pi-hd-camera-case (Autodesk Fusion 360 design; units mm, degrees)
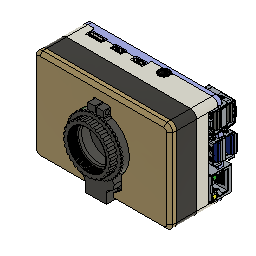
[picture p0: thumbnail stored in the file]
parameter "thickness" = 1.5
parameter "gap" = 0.2
parameter "boxWidth" = 86
parameter "boxHeight" = 57
parameter "boxDepth" = 50
base_feature "Base Feature1"
base_feature "Base Feature1"
base_feature "Base Feature1"
base_feature "Base Feature1"
base_feature "Base Feature1"
base_feature "Base Feature1"
base_feature "Base Feature1"
base_feature "Base Feature1"
base_feature "Base Feature1"
base_feature "Base Feature1"
base_feature "Base Feature1"
place_component Linear Dimension-11 20
base_feature "Base Feature1"
base_feature "Base Feature1"
base_feature "Base Feature1"
base_feature "Base Feature1"
base_feature "Base Feature1"
base_feature "Base Feature1"
base_feature "Base Feature1"
as_built_joint "As-built1"
base_feature "Base Feature1"
sketch "base" plane through (0, 0, 0) normal (0, 1, 0) x axis (1, 0, 0)
  line L1 (43, -28.5) -> (-43, -28.5)
  line L2 (43, 28.5) -> (43, -28.5)
  line L3 (-43, 28.5) -> (43, 28.5)
  line L4 (-43, -28.5) -> (-43, 28.5)
  line L5 (0, 0) -> (0, -28.5)
  line L6 (43, 0) -> (0, 0)
  line L7 (15, -15) -> (-15, -15)
  line L8 (-15, 15) -> (-15, -15)
  line L9 (15, 15) -> (15, -15)
  line L10 (-15, 15) -> (15, 15)
  line L11 (0, 0) -> (0, 15)
  line L12 (0, 0) -> (-15, 0)
  line L13 (-44.5, 30) -> (44.5, 30)
  line L14 (-44.5, -30) -> (-44.5, 30)
  line L15 (44.5, -30) -> (-44.5, -30)
  line L16 (44.5, 30) -> (44.5, -30)
  circle C1 centre (-39, -24.5) radius 1.5
  circle C2 centre (-15, -15) radius 1.5
  circle C3 centre (15, -15) radius 1.5
  circle C4 centre (-15, 15) radius 1.5
  circle C5 centre (15, 15) radius 1.5
  point P6 (0, -28.5)
  point P1 (0, 0)
  point P7 (0, 0)
  point P8 (43, 0)
  point P10 (-15, -15)
  point P11 (-15, -15)
  point P12 (15, -15)
  point P13 (15, -15)
  point P14 (-15, -15)
  point P15 (-15, 15)
  point P16 (-15, 15)
  point P17 (15, -15)
  point P19 (-15, 15)
  point P18 (15, 15)
  point P20 (15, 15)
  point P21 (0, 15)
  point P22 (0, 0)
  point P23 (-15, 0)
  point P24 (0, 0)
  point P2 (-43, -28.5)
  point P3 (43, -28.5)
  point P5 (-43, 28.5)
  point P9 (-39, -24.5)
  horizontal L1
  vertical L2
  horizontal L3
  vertical L4
  midpoint L1 P6
  coincident P1 P7
  midpoint L2 P8
  vertical L5
  horizontal L6
  coincident P10 P11
  horizontal L7
  coincident P12 P13
  coincident P10 P14
  perpendicular L7 L8
  coincident P15 P16
  coincident P13 P17
  perpendicular L7 L9
  coincident P16 P19
  perpendicular L9 L10
  coincident P18 P20
  midpoint L10 P21
  coincident P1 P22
  vertical L11
  midpoint L8 P23
  coincident P1 P24
  horizontal L12
  dimension "d6" distance P2 P3 = 86 (= "boxWidth")
  dimension "d7" distance P2 P5 = 57 (= "boxHeight")
  dimension "d8" diameter C1 = 3
  dimension "d9" distance L1 P9 = 4
  dimension "d10" distance L4 P9 = 4
  dimension "d11" diameter C2 = 3
  dimension "d12" diameter C3 = 3
  dimension "d13" distance P11 P12 = 30
  dimension "d14" distance P14 P15 = 30
  dimension "d15" diameter C4 = 3
  dimension "d16" diameter C5 = 3
  dimension "d97" = 1.5 (= "thickness")
  dimension "d33" OffsetX = 0
  dimension "d34" OffsetY = 0
  dimension "d35" OffsetZ = 0
  dimension "d36" AngleZ = 0
  dimension "d79" OffsetX = 0
  dimension "d80" OffsetY = 0
  dimension "d81" OffsetZ = 0
  dimension "d82" AngleZ = 0
joint "Assemble1" OffsetX 0 OffsetY 0 OffsetZ 0 AngleZ 0 alignAngle 0 alignOffsetX 0 alignOffsetY 0 alignOffsetZ 0
joint "Assemble2" OffsetX 0 OffsetY 0 OffsetZ 0 AngleZ 0 alignAngle 0 alignOffsetX 0 alignOffsetY 0 alignOffsetZ -17 OffsetX 0 OffsetY 0 OffsetZ 0 AngleZ 0 OffsetX 0 OffsetY 0 OffsetZ 0 AngleZ 0
sketch "Sketch1" plane through (0, 0, 0) normal (0, 1, 0) x axis (1, 0, 0)
  line L1 (19, -24.5) -> (-39, -24.5)
  line L2 (-39, 24.5) -> (19, 24.5)
  line L3 (-39, -24.5) -> (-39, 24.5)
  line L4 (15, -15) -> (-15, -15)
  line L5 (15, 14.9769) -> (15, -15)
  line L6 (-15, 14.9769) -> (15, 14.9769)
  line L7 (-15, -15) -> (-15, 14.9769)
  line L8 (-39, -9) -> (-15, -9)
  line L9 (-9, -24.5) -> (-9, -15)
  line L10 (-9, 24.5) -> (-9, 14.9769)
  line L11 (39, -24.5) -> (19, -24.5)
  line L12 (39, 24.5) -> (39, -24.5)
  line L13 (19, 24.5) -> (39, 24.5)
  line L14 (39, -9) -> (15, -9)
  line L15 (9, -15) -> (9, -24.5)
  line L16 (-15, 8.9769) -> (-39, 8.9769)
  line L17 (39, 8.9769) -> (15, 8.9769)
  line L18 (9, 24.5) -> (9, 14.9769)
  circle C1 centre (-39, -24.5) radius 1.35
  circle C2 centre (19, -24.5) radius 1.35
  circle C3 centre (15, -15) radius 1.25
  circle C4 centre (-15, -15) radius 1.25
  circle C5 centre (-15, 14.9769) radius 1.25
  circle C6 centre (15, 14.9769) radius 1.25
  circle C7 centre (19, 24.5) radius 1.35
  circle C8 centre (-39, 24.5) radius 1.35
  circle C9 centre (-39, -24.5) radius 1.75
  circle C10 centre (-39, -24.5) radius 3.25
  circle C11 centre (-39, 24.5) radius 1.75
  circle C12 centre (-39, 24.5) radius 3.25
  circle C13 centre (-15, 14.9769) radius 1.5
  circle C14 centre (-15, 14.9769) radius 3
  circle C15 centre (-15, -15) radius 1.5
  circle C16 centre (-15, -15) radius 3
  circle C17 centre (19, -24.5) radius 1.75
  circle C18 centre (19, -24.5) radius 3.25
  circle C19 centre (15, -15) radius 1.5
  circle C20 centre (15, -15) radius 3
  circle C21 centre (15, 14.9769) radius 1.5
  circle C22 centre (15, 14.9769) radius 3
  circle C23 centre (19, 24.5) radius 1.75
  circle C24 centre (19, 24.5) radius 3.25
  circle C25 centre (39, 24.5) radius 1.75
  circle C26 centre (39, 24.5) radius 3.25
  circle C27 centre (39, -24.5) radius 1.75
  circle C28 centre (39, -24.5) radius 3.25
  circle C29 centre (-29, 24.5) radius 1.75
  circle C30 centre (-29, 24.5) radius 3.25
  circle C31 centre (-29, -24.5) radius 1.75
  circle C32 centre (-29, -24.5) radius 3.25
  point P2 (-39, -24.5)
  point P10 (-39, -24.5)
  point P3 (19, -24.5)
  point P11 (19, -24.5)
  point P8 (19, 24.5)
  point P12 (19, 24.5)
  point P9 (-39, 24.5)
  point P13 (-39, 24.5)
  point P5 (-15, -15)
  point P14 (-15, -15)
  point P4 (15, -15)
  point P15 (15, -15)
  point P7 (15, 14.9769)
  point P16 (15, 14.9769)
  point P6 (-15, 14.9769)
  point P17 (-15, 14.9769)
  point P18 (-15, -15)
  point P20 (-39, -9)
  point P22 (-9, -24.5)
  point P24 (-9, 24.5)
  point P25 (-39, -24.5)
  point P27 (-39, 24.5)
  point P31 (-15, -15)
  point P33 (19, -24.5)
  point P37 (15, 14.9769)
  point P39 (19, 24.5)
  point P41 (19, -24.5)
  point P44 (19, 24.5)
  point P46 (39, -9)
  point P47 (9, -24.5)
  point P48 (9, -15)
  point P49 (-39, 8.9769)
  point P50 (-15, 8.9769)
  point P51 (15, 8.9769)
  point P52 (39, 8.9769)
  point P53 (9, 14.9769)
  point P54 (9, 24.5)
  point P43 (39, 24.5)
  point P55 (39, 24.5)
  point P42 (39, -24.5)
  point P57 (39, -24.5)
  point P61 (-29, -24.5)
  point P59 (-29, 24.5)
  point P35 (15, -15)
  point P29 (-15, 14.9769)
  point P62 (-29, -24.5)
  point P63 (-39, -24.5)
  point P60 (-29, 24.5)
  coincident P2 P10
  coincident P3 P11
  coincident P8 P12
  coincident P9 P13
  coincident P5 P14
  coincident P4 P15
  coincident P7 P16
  coincident P6 P17
  coincident P5 P18
  coincident L3 P20
  perpendicular L3 L8
  coincident L1 P22
  perpendicular L1 L9
  coincident L2 P24
  perpendicular L6 L10
  coincident P10 P25
  coincident P13 P27
  concentric C5 C13
  coincident P18 P31
  coincident P11 P33
  concentric C3 C19
  coincident P16 P37
  coincident P12 P39
  coincident P33 P41
  parallel L1 L11
  perpendicular L1 L12
  coincident P39 P44
  perpendicular L12 L13
  coincident L12 P46
  perpendicular L12 L14
  coincident L1 P47
  coincident L4 P48
  perpendicular L4 L15
  coincident L3 P49
  coincident L7 P50
  perpendicular L7 L16
  coincident L5 P51
  coincident L12 P52
  perpendicular L12 L17
  coincident L6 P53
  coincident L2 P54
  perpendicular L2 L18
  coincident P43 P55
  coincident P42 P57
  coincident L1 P61
  coincident L2 P59
  dimension "d42" diameter C9 = 3.5
  dimension "d43" = 1.5 (= "thickness")
  dimension "d44" diameter C11 = 3.5
  dimension "d45" = 1.5 (= "thickness")
  dimension "d46" diameter C13 = 3
  dimension "d47" distance C13 = 1.5 (= "thickness")
  dimension "d48" diameter C15 = 3
  dimension "d49" distance C15 = 1.5 (= "thickness")
  dimension "d50" diameter C17 = 3.5
  dimension "d51" = 1.5 (= "thickness")
  dimension "d52" diameter C19 = 3
  dimension "d53" distance C19 = 1.5 (= "thickness")
  dimension "d54" diameter C21 = 3
  dimension "d55" distance C21 = 1.5 (= "thickness")
  dimension "d56" diameter C23 = 3.5
  dimension "d57" = 1.5 (= "thickness")
  dimension "d63" distance P41 P42 = 20
  dimension "d89" distance P35 L14 = 6
  dimension "d90" distance P16 L17 = 6
  dimension "d91" distance P14 L8 = 6
  dimension "d92" distance P29 L16 = 6
  dimension "d93" distance L10 P29 = 6
  dimension "d94" distance P16 L18 = 6
  dimension "d95" distance P35 L15 = 6
  dimension "d96" distance P14 L9 = 6
  dimension "d150" diameter C25 = 3.5
  dimension "d151" = 1.5 (= "thickness")
  dimension "d153" diameter C27 = 3.5
  dimension "d154" = 1.5 (= "thickness")
  dimension "d156" diameter C29 = 3.5
  dimension "d158" = 1.5 (= "thickness")
  dimension "d159" diameter C31 = 3.5
  dimension "d160" = 1.5 (= "thickness")
  dimension "d162" distance P62 P63 = 10
  dimension "d266" distance P13 P60 = 10
extrude "Extrude3" new body blind -2 from offset -3
thicken "Thicken2" Thickness 1
extrude "Extrude4" add sketch "Sketch1" profile of L1 L2 L3 C9 C10 C11 C12 C17 C18 C23 C24 L11 L13 to an object
extrude "Extrude6" sketch "Sketch1" profile of L1 L2 L4 L5 L6 L7 C13 C14 C15 C16 C19 C20 C21 C22 L11 L12 L13 C25 C26 C27 C28 C29 C30 C31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 to an object
extrude "Extrude5" cut sketch "Sketch1" profile of L1 L2 L3 L4 L5 L6 L7 C9 C11 C13 C15 C17 C19 C21 C23 L11 L12 L13 C25 C27 C29 C31 to an object
fillet "Fillet1" radius 1
sketch "Sketch1" plane through (0, 0, 0) normal (0, 1, 0) x axis (1, 0, 0)
  line L1 (-15, -12.1132) -> (-12.5, -13.5566)
  line L2 (-17.5, -13.5566) -> (-15, -12.1132)
  line L3 (-17.5, -16.4434) -> (-17.5, -13.5566)
  line L4 (-15, -17.8868) -> (-17.5, -16.4434)
  line L5 (-12.5, -16.4434) -> (-15, -17.8868)
  line L6 (-12.5, -13.5566) -> (-12.5, -16.4434)
  line L7 (0, -10) -> (0, 0)
  line L8 (17.5, -16.4434) -> (17.5, -13.5566)
  line L9 (15, -17.8868) -> (17.5, -16.4434)
  line L10 (12.5, -16.4434) -> (15, -17.8868)
  line L11 (12.5, -13.5566) -> (12.5, -16.4434)
  line L12 (15, -12.1132) -> (12.5, -13.5566)
  line L13 (17.5, -13.5566) -> (15, -12.1132)
  line L14 (10, 0) -> (0, 0)
  line L15 (17.5, 16.4434) -> (17.5, 13.5566)
  line L16 (15, 17.8868) -> (17.5, 16.4434)
  line L17 (12.5, 16.4434) -> (15, 17.8868)
  line L18 (12.5, 13.5566) -> (12.5, 16.4434)
  line L19 (15, 12.1132) -> (12.5, 13.5566)
  line L20 (17.5, 13.5566) -> (15, 12.1132)
  line L21 (-17.5, 16.4434) -> (-17.5, 13.5566)
  line L22 (-15, 17.8868) -> (-17.5, 16.4434)
  line L23 (-12.5, 16.4434) -> (-15, 17.8868)
  line L24 (-12.5, 13.5566) -> (-12.5, 16.4434)
  line L25 (-17.5, 13.5566) -> (-15, 12.1132)
  line L26 (-15, 12.1132) -> (-12.5, 13.5566)
  circle C1 centre (-15, -15) radius 1.5
  circle C2 centre (15, -15) radius 1.5
  circle C3 centre (15, 14.9769) radius 1.5
  circle C4 centre (-15, 14.9769) radius 1.5
  point P2 (-15, -15)
  point P12 (-15, -15)
  point P1 (0, 0)
  point P13 (0, 0)
  point P6 (-12.5, -13.5566)
  point P19 (12.5, -13.5566)
  point P7 (-15, -12.1132)
  point P20 (15, -12.1132)
  point P8 (-17.5, -13.5566)
  point P15 (17.5, -13.5566)
  point P9 (-17.5, -16.4434)
  point P16 (17.5, -16.4434)
  point P10 (-15, -17.8868)
  point P17 (15, -17.8868)
  point P11 (-12.5, -16.4434)
  point P18 (12.5, -16.4434)
  point P21 (0, 0)
  point P33 (-12.5, 13.5566)
  point P34 (-15, 12.1132)
  point P29 (-17.5, 13.5566)
  point P30 (-17.5, 16.4434)
  point P31 (-15, 17.8868)
  point P32 (-12.5, 16.4434)
  point P23 (17.5, 13.5566)
  point P24 (17.5, 16.4434)
  point P25 (15, 17.8868)
  point P26 (12.5, 16.4434)
  point P27 (12.5, 13.5566)
  point P28 (15, 12.1132)
  coincident P2 P12
  vertical L6
  coincident P1 P13
  vertical L7
  symmetric P6 L7 P19
  symmetric P7 L7 P20
  symmetric P8 L7 P15
  symmetric P9 L7 P16
  symmetric P10 L7 P17
  symmetric P11 L7 P18
  coincident P1 P21
  perpendicular L7 L14
  symmetric P6 L14 P33
  symmetric P7 L14 P34
  symmetric P8 L14 P29
  symmetric P9 L14 P30
  symmetric P10 L14 P31
  symmetric P11 L14 P32
  symmetric P15 L14 P23
  symmetric P16 L14 P24
  symmetric P17 L14 P25
  symmetric P18 L14 P26
  symmetric P19 L14 P27
  symmetric P20 L14 P28
  dimension "d85" distance P12 L6 = 2.5
extrude "Extrude1" sketch "Sketch1" profile of C1 C2 C3 C4 L1 L2 L3 L4 L5 L6 L8 L9 L10 L11 L12 L13 L15 L16 L17 L18 L19 L20 L21 L22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 blind -12
base_feature "Base Feature1"
rectangular_pattern "" uSpaceDistance 7 vSpaceDistance 0
joint "Assemble3" alignAngle 0 alignOffsetX 0 alignOffsetY 0 alignOffsetZ 0
joint "Assemble4" alignAngle 0 alignOffsetX 0 alignOffsetY 0 alignOffsetZ 0
joint "Assemble5" alignAngle 0 alignOffsetX 0 alignOffsetY 0 alignOffsetZ 0
joint "Assemble6" alignAngle 0 alignOffsetX 0 alignOffsetY 0 alignOffsetZ 0
joint "Assemble7" OffsetX 0 OffsetY 0 OffsetZ 0 AngleZ 0 alignAngle 0 alignOffsetX 0 alignOffsetY 0 alignOffsetZ 0
joint "Assemble8" OffsetX 0 OffsetY 0 OffsetZ 0 AngleZ 0 alignAngle 0 alignOffsetX 0 alignOffsetY 0 alignOffsetZ 0
joint "Assemble9" OffsetX 0 OffsetY 0 OffsetZ 0 AngleZ 0 alignAngle 0 alignOffsetX 0 alignOffsetY 0 alignOffsetZ 0
joint "Assemble10" OffsetX 0 OffsetY 0 OffsetZ 0 AngleZ 0 alignAngle 0 alignOffsetX 0 alignOffsetY 0 alignOffsetZ 0
base_feature "Base Feature1"
rectangular_pattern "ꨁ225" uSpaceDistance 9 vSpaceDistance 0
joint "Assemble11" OffsetX 0 OffsetY 0 OffsetZ 0 AngleZ 0 alignAngle 0 alignOffsetX 0 alignOffsetY 0 alignOffsetZ 0
joint "Assemble12" OffsetX 0 OffsetY 0 OffsetZ 0 AngleZ 0 alignAngle 0 alignOffsetX 0 alignOffsetY 0 alignOffsetZ 0
joint "Assemble13" OffsetX 0 OffsetY 0 OffsetZ 0 AngleZ 0 alignAngle 0 alignOffsetX 0 alignOffsetY 0 alignOffsetZ 0
joint "Assemble14" OffsetX 0 OffsetY 0 OffsetZ 0 AngleZ 0 alignAngle 0 alignOffsetX 0 alignOffsetY 0 alignOffsetZ 0
base_feature "Base Feature1"
rectangular_pattern "甁" uSpaceDistance 7 vSpaceDistance 0
joint "Assemble15" alignAngle 0 alignOffsetX 0 alignOffsetY 0 alignOffsetZ 0
joint "Assemble16" alignAngle 0 alignOffsetX 0 alignOffsetY 0 alignOffsetZ 0
joint "Assemble17" alignAngle 0 alignOffsetX 0 alignOffsetY 0 alignOffsetZ 0
joint "Assemble18" alignAngle 0 alignOffsetX 0 alignOffsetY 0 alignOffsetZ 0
extrude "Extrude1" new body sketch "base" profile of L1 L2 L3 L4 L16 L14 L15 L13 blind -14 from offset 7
fillet "Fillet2" radius 2.5 4
sketch "usb ports" plane through (44.5, 0, 0) normal (1, 0, 0) x axis (0, 1, 0)
  line L1 (7, -26) -> (7, 26)
  line L2 (1, 26) -> (7, 26)
  line L3 (1, -26) -> (1, 26)
  line L4 (7, -26) -> (1, -26)
  point P7 (7, -26)
  point P5 (1, -26)
  point P6 (1, -26)
  point P3 (7, -26)
  point P2 (7, 26)
  point P8 (7, 26)
  point P4 (1, 26)
  perpendicular L1 L2
  perpendicular L2 L3
  coincident L1 P7
  perpendicular L1 L4
  coincident P5 P6
  coincident P3 L4
  coincident P2 P8
  dimension "d122" distance P2 P4 = 6
extrude "Extrude4" cut sketch "usb ports" against normal blind 3
sketch "top ports" plane through (0, 0, 30) normal (0, 0, 1) x axis (-1, 0, 0)
  line L1 (7, -1) -> (-1, -1)
  line L2 (7, -7) -> (7, -1)
  line L3 (-1, -7) -> (7, -7)
  line L4 (-1, -1) -> (-1, -7)
  line L5 (20, -1) -> (13, -1)
  line L6 (20, -7) -> (20, -1)
  line L7 (13, -7) -> (20, -7)
  line L8 (13, -1) -> (13, -7)
  line L9 (36, -1) -> (26, -1)
  line L10 (36, -7) -> (36, -1)
  line L11 (26, -7) -> (36, -7)
  line L12 (26, -1) -> (26, -7)
  circle C1 centre (-11.5, -4.59) radius 2.1
  circle C2 centre (-11.5, -4.59) radius 3.5
  concentric C1 C2
  horizontal L1
  vertical L2
  horizontal L3
  vertical L4
  horizontal L5
  vertical L6
  horizontal L7
  vertical L8
  horizontal L9
  vertical L10
  horizontal L11
  vertical L12
  dimension "d123" diameter C2 = 7
extrude "Extrude5" cut sketch "top ports" no distance stored
fillet "Fillet3" radius 1
extrude "Extrude6" cut of existing geometry blind -3
sketch "sdcard" plane through (-44.5, 0, 0) normal (-1, 0, 0) x axis (0, -1, 0)
  line L1 (2, 7.3) -> (-1, 7.3)
  line L2 (2, -7.7) -> (2, 7.3)
  line L3 (-1, -7.7) -> (2, -7.7)
  line L4 (-1, 7.3) -> (-1, -7.7)
  line L5 (0, -0.2) -> (-1, -0.2)
  line L6 (0, 0) -> (0, -0.2)
  line L7 (5, 4.3) -> (2, 4.3)
  line L8 (5, -4.7) -> (5, 4.3)
  line L9 (2, -4.7) -> (5, -4.7)
  line L10 (2, -0.2) -> (5, -0.2)
  line L11 (-4, 4.3) -> (-1, 4.3)
  line L12 (-4, -4.7) -> (-4, 4.3)
  line L13 (-1, -4.7) -> (-4, -4.7)
  line L14 (-1, -0.2) -> (-4, -0.2)
  point P6 (-1, -0.2)
  point P1 (0, 0)
  point P8 (0, 0)
  point P9 (2, 4.3)
  point P12 (2, -4.7)
  point P13 (5, -0.2)
  point P14 (2, -0.2)
  point P15 (-1, 4.3)
  point P18 (-1, -4.7)
  point P19 (-4, -0.2)
  point P3 (2, 7.3)
  point P4 (2, -7.7)
  point P2 (-1, 7.3)
  point P7 (0, -0.2)
  point P10 (5, 4.3)
  point P11 (5, -4.7)
  point P16 (-4, 4.3)
  point P17 (-4, -4.7)
  horizontal L1
  vertical L2
  horizontal L3
  vertical L4
  midpoint L4 P6
  perpendicular L4 L5
  coincident P1 P8
  perpendicular L5 L6
  coincident L2 P9
  perpendicular L2 L7
  perpendicular L7 L8
  coincident L2 P12
  perpendicular L2 L9
  midpoint L8 P13
  midpoint L2 P14
  horizontal L10
  coincident L4 P15
  perpendicular L4 L11
  perpendicular L11 L12
  coincident L4 P18
  perpendicular L4 L13
  midpoint L12 P19
  horizontal L14
  dimension "d129" distance P3 P4 = 15
  dimension "d130" distance P2 P3 = 3
  dimension "d133" distance P6 P7 = 1
  dimension "d176" distance P10 P11 = 9
  dimension "d177" distance P9 P10 = 3
  dimension "d179" distance P16 P17 = 9
  dimension "d180" distance P15 P16 = 3
  dimension "d417" distance P7 P8 = 0.2
extrude "Extrude7" cut sketch "sdcard" profile of L1 L2 L3 L4 L7 L8 L9 L11 L12 L13 no distance stored
fillet "Fillet5" radius 1.5 1.6
fillet "Fillet6" radius 1
sketch "tabs" plane through (0, -7, 0) normal (0, -1, 0) x axis (1, 0, 0)
  line L1 (44.5, 30) -> (-44.5, 30)
  line L2 (44.5, -30) -> (44.5, 30)
  line L3 (-44.5, -30) -> (44.5, -30)
  line L4 (-44.5, 30) -> (-44.5, -30)
  line L5 (0, 0) -> (0, 30)
  line L6 (44.5, 0) -> (0, 0)
  line L7 (-32.25, 21.25) -> (-32.25, 30)
  line L8 (-25.75, 21.25) -> (-32.25, 21.25)
  line L9 (-25.75, 30) -> (-25.75, 21.25)
  line L10 (-29, 24.5) -> (-29, 21.25)
  line L11 (-32.25, -21.25) -> (-32.25, -30)
  line L12 (-25.75, -21.25) -> (-32.25, -21.25)
  line L13 (-25.75, -30) -> (-25.75, -21.25)
  line L14 (-29, -21.25) -> (-29, -24.5)
  line L15 (35.75, -21.25) -> (44.5, -21.25)
  line L16 (35.75, -27.75) -> (35.75, -21.25)
  line L17 (44.5, -27.75) -> (35.75, -27.75)
  line L18 (39, -24.5) -> (35.75, -24.5)
  line L19 (35.75, 21.25) -> (35.75, 30)
  line L20 (44.5, 21.25) -> (35.75, 21.25)
  line L21 (39, 24.5) -> (35.75, 24.5)
  line L22 (43, -26) -> (43, 26)
  line L23 (40.5, 28.5) -> (-40.5, 28.5)
  circle C1 centre (-29, 24.5) radius 1.75
  circle C2 centre (-29, -24.5) radius 1.75
  circle C3 centre (39, 24.5) radius 1.75
  circle C4 centre (39, -24.5) radius 1.75
  arc A1 centre (40.5, 26) radius 2.5 clockwise from (40.5, 28.5) to (43, 26)
  arc A2 centre (40.5, -26) radius 2.5 clockwise from (43, -26) to (40.5, -28.5)
  point P6 (0, 30)
  point P1 (0, 0)
  point P7 (0, 0)
  point P8 (44.5, 0)
  point P13 (-32.25, 30)
  point P16 (-25.75, 30)
  point P17 (-29, 21.25)
  point P9 (-29, 24.5)
  point P18 (-29, 24.5)
  point P19 (-32.25, -30)
  point P22 (-25.75, -30)
  point P10 (-29, -24.5)
  point P23 (-29, -24.5)
  point P24 (-29, -21.25)
  point P25 (44.5, -21.25)
  point P28 (44.5, -27.75)
  point P29 (35.75, -24.5)
  point P12 (39, -24.5)
  point P30 (39, -24.5)
  point P33 (44.5, 21.25)
  point P11 (39, 24.5)
  point P35 (39, 24.5)
  point P31 (35.75, 30)
  point P34 (35.75, 24.5)
  point P2 (-44.5, 30)
  point P3 (44.5, 30)
  point P4 (44.5, -30)
  point P14 (-32.25, 21.25)
  point P15 (-25.75, 21.25)
  point P20 (-32.25, -21.25)
  point P21 (-25.75, -21.25)
  point P26 (35.75, -21.25)
  point P27 (35.75, -27.75)
  horizontal L1
  vertical L2
  horizontal L3
  vertical L4
  midpoint L1 P6
  coincident P1 P7
  midpoint L2 P8
  horizontal L6
  vertical L5
  coincident L1 P13
  perpendicular L1 L7
  perpendicular L7 L8
  coincident L1 P16
  perpendicular L1 L9
  midpoint L8 P17
  coincident P9 P18
  vertical L10
  coincident L3 P19
  perpendicular L3 L11
  perpendicular L11 L12
  coincident L3 P22
  perpendicular L3 L13
  coincident P10 P23
  midpoint L12 P24
  vertical L14
  coincident L2 P25
  perpendicular L2 L15
  perpendicular L15 L16
  coincident L2 P28
  perpendicular L2 L17
  midpoint L16 P29
  coincident P12 P30
  horizontal L18
  perpendicular L2 L20
  coincident L2 P33
  coincident P11 P35
  horizontal L21
  coincident L1 P31
  coincident L19 P34
  perpendicular L1 L19
  dimension "d138" distance P2 P3 = 89 (= "boxWidth + ( thickness * 2 )")
  dimension "d139" distance P3 P4 = 60 (= "boxHeight + ( thickness * 2 )")
  dimension "d163" distance P17 P18 = 3.25
  dimension "d164" distance P14 P15 = 6.5
  dimension "d165" distance P23 P24 = 3.25
  dimension "d166" distance P20 P21 = 6.5
  dimension "d167" distance P29 P30 = 3.25
  dimension "d168" distance P26 P27 = 6.5
  dimension "d169" distance P34 P35 = 3.25
  dimension "d174" distance L20 L21 = 3.25
extrude "Extrude9" add sketch "tabs" profile of L1 L3 C1 C2 C3 C4 L7 L8 L9 L11 L12 L13 L15 L16 L17 L19 L20 A1 L22 L23 A2 against normal blind 2
fillet "Fillet9" radius 3.25 1.5 (= "thickness")
sketch "snaps" plane through (0, 0, 0) normal (1, 0, 0) x axis (0, 1, 0)
  line L1 (-7, 28.5) -> (-5, 28.5)
  line L2 (-6, 27.5) -> (-7, 28.5)
  line L3 (-5, 28.5) -> (-6, 27.5)
  line L4 (0, 28.5) -> (0, 0)
  line L5 (-5, 28.5) -> (0, 28.5)
  line L6 (-6, 0) -> (0, 0)
  line L7 (-6, -27.5) -> (-7, -28.5)
  line L8 (-5, -28.5) -> (-6, -27.5)
  line L9 (-7, -28.5) -> (-5, -28.5)
  point P1 (0, 0)
  point P5 (0, 0)
  point P7 (0, 0)
  point P2 (-5, 28.5)
  point P11 (-5, -28.5)
  point P3 (-7, 28.5)
  point P9 (-7, -28.5)
  point P4 (-6, 27.5)
  point P10 (-6, -27.5)
  horizontal L1
  perpendicular L2 L3
  coincident P1 P5
  vertical L4
  perpendicular L4 L5
  coincident P1 P7
  perpendicular L4 L6
  symmetric P2 L6 P11
  symmetric P3 L6 P9
  symmetric P4 L6 P10
  dimension "d198" angle L1 L3 = 45
  dimension "d199" distance P2 P3 = 2
  dimension "d200" distance P1 L1 = 28.5 (= "boxHeight / 2")
  dimension "d201" distance P1 P3 = 7
extrude "Extrude10" add sketch "snaps" profile of L7 L8 L9 distance 16 from offset -4
work_plane "WorkPlane1" AlongDistance 0
sketch "base" plane through (0, -7, 0) normal (0, -1, 0) x axis (1, 0, 0)
  line L1 (44.5, 30) -> (-44.5, 30)
  line L2 (44.5, -30) -> (44.5, 30)
  line L3 (-44.5, -30) -> (44.5, -30)
  line L4 (-44.5, 30) -> (-44.5, -30)
  line L5 (0, 0) -> (0, 30)
  line L6 (44.5, 0) -> (0, 0)
  line L7 (-43, -28.5) -> (43, -28.5)
  line L8 (-43, 28.5) -> (-43, -28.5)
  line L9 (43, 28.5) -> (-43, 28.5)
  line L10 (43, -28.5) -> (43, 28.5)
  point P6 (0, 30)
  point P1 (0, 0)
  point P7 (0, 0)
  point P8 (44.5, 0)
  point P2 (-44.5, 30)
  point P3 (44.5, 30)
  point P5 (-44.5, -30)
  horizontal L1
  vertical L2
  horizontal L3
  vertical L4
  midpoint L1 P6
  coincident P1 P7
  midpoint L2 P8
  horizontal L6
  vertical L5
  dimension "d182" distance P2 P3 = 89 (= "boxWidth + ( thickness * 2 )")
  dimension "d183" distance P2 P5 = 60 (= "boxHeight + ( thickness * 2 )")
  dimension "d184" = 1.5 (= "thickness")
extrude "Extrude1" new body sketch "base" profile of L1 L2 L3 L4 L10 L9 L8 L7 along normal blind 13
fillet "Fillet1" radius 2.5 4
sketch "snaps" plane through (0, 0, 0) normal (1, 0, 0) x axis (0, 1, 0)
  line L1 (-6, 27.5) -> (-7, 28.5)
  line L2 (-5, 28.5) -> (-6, 27.5)
  line L3 (-3.9393, 27.4393) -> (-5, 28.5)
  line L4 (-6, 25.3787) -> (-3.9393, 27.4393)
  line L5 (-9.1213, 28.5) -> (-6, 25.3787)
  line L6 (-7, 28.5) -> (-9.1213, 28.5)
  line L7 (-7, 28.5) -> (-5, 28.5)
  line L8 (36, 0) -> (0, 0)
  line L9 (-7, -28.5) -> (-9.1213, -28.5)
  line L10 (-6, -27.5) -> (-7, -28.5)
  line L11 (-5, -28.5) -> (-6, -27.5)
  line L12 (-3.9393, -27.4393) -> (-5, -28.5)
  line L13 (-6, -25.3787) -> (-3.9393, -27.4393)
  line L14 (-9.1213, -28.5) -> (-6, -25.3787)
  line L15 (-20, 28.5) -> (-18, 28.5)
  line L16 (-19, 27.5) -> (-20, 28.5)
  line L17 (-18, 28.5) -> (-19, 27.5)
  line L18 (-20, -28.5) -> (-18, -28.5)
  line L19 (-19, -27.5) -> (-20, -28.5)
  line L20 (-18, -28.5) -> (-19, -27.5)
  point P1 (0, 0)
  point P8 (0, 0)
  point P2 (-7, 28.5)
  point P11 (-7, -28.5)
  point P3 (-6, 27.5)
  point P12 (-6, -27.5)
  point P4 (-5, 28.5)
  point P13 (-5, -28.5)
  point P5 (-3.9393, 27.4393)
  point P14 (-3.9393, -27.4393)
  point P6 (-6, 25.3787)
  point P15 (-6, -25.3787)
  point P7 (-9.1213, 28.5)
  point P10 (-9.1213, -28.5)
  point P16 (-18, 28.5)
  point P17 (-20, 28.5)
  point P19 (-18, -28.5)
  point P20 (-20, -28.5)
  perpendicular L1 L2
  perpendicular L2 L3
  perpendicular L3 L4
  perpendicular L4 L5
  horizontal L6
  parallel L6 L7
  coincident P1 P8
  horizontal L8
  symmetric P2 L8 P11
  symmetric P3 L8 P12
  symmetric P4 L8 P13
  symmetric P5 L8 P14
  symmetric P6 L8 P15
  symmetric P7 L8 P10
  horizontal L15
  perpendicular L16 L17
  horizontal L18
  perpendicular L19 L20
  dimension "d205" distance P2 P4 = 2
  dimension "d206" distance P4 P5 = 1.5 (= "thickness")
  dimension "d207" distance L1 L5 = 1.5 (= "thickness")
  dimension "d208" distance P1 L6 = 28.5 (= "boxHeight / 2")
  dimension "d209" distance P1 P2 = 7
  dimension "d210" angle L5 L6 = 45
  dimension "d241" angle L15 L17 = 45
  dimension "d242" distance P16 P17 = 2
  dimension "d243" distance L8 L15 = 28.5 (= "boxHeight / 2")
  dimension "d244" distance P1 P17 = 20
  dimension "d258" angle L18 L20 = 45
  dimension "d259" distance P19 P20 = 2
  dimension "d260" distance P1 P20 = 20
  dimension "d261" distance P1 P19 = 28.5 (= "boxHeight / 2")
extrude "Extrude2" add sketch "snaps" profile of L1 L2 L3 L4 L5 L6 along normal blind 14 and against normal blind 20
extrude "Extrude4" add sketch "snaps" profile of L9 L10 L11 L12 L13 L14 distance 16 from offset -4
offset_faces "OffsetFaces5" distance 0.2 (= "gap")
offset_faces "OffsetFaces6"
fillet "Fillet4" radius 0.5
sketch "side tabs" plane through (0, 0, 0) normal (0, 0, 1) x axis (1, 0, 0)
  line L1 (43, -4) -> (43, -10)
  line L2 (41.5, -4) -> (43, -4)
  line L3 (41.5, -8.5) -> (41.5, -4)
  line L4 (43, -10) -> (41.5, -8.5)
  line L5 (43, -20) -> (43, -18)
  line L6 (42, -19) -> (43, -20)
  line L7 (43, -18) -> (42, -19)
  point P2 (43, -4)
  point P3 (41.5, -4)
  point P5 (43, -10)
  point P1 (0, 0)
  point P7 (43, -20)
  point P6 (43, -18)
  vertical L1
  perpendicular L1 L2
  perpendicular L2 L3
  vertical L5
  perpendicular L6 L7
  dimension "d218" angle L1 L4 = 45
  dimension "d219" distance P2 P3 = 1.5 (= "thickness")
  dimension "d220" distance P2 P5 = 6
  dimension "d221" distance P1 L1 = 43 (= "boxWidth / 2")
  dimension "d222" distance P1 L2 = 4
  dimension "d248" angle L5 L6 = 45
  dimension "d249" distance P1 P7 = 20
  dimension "d250" distance P1 L5 = 43 (= "boxWidth / 2")
  dimension "d251" distance P6 P7 = 2
extrude "Extrude3" add sketch "side tabs" profile of L1 L2 L3 L4 distance 14
fillet "Fillet3" radius 1.5 (= "thickness")
offset_faces "OffsetFaces3" distance 0.2 (= "gap")
offset_faces "OffsetFaces4"
mirror "Mirror2"
extrude "Extrude11" add sketch "snaps" profile of L1 L2 L3 along normal blind 14 and against normal blind 20
extrude "Extrude5" add sketch "snaps" profile of L15 L16 L17 distance 30
extrude "Extrude6" add sketch "side tabs" profile of L5 L6 L7 distance 20
mirror "Mirror4"
extrude "Extrude8" add sketch "snaps" profile of L18 L19 L20 blind 18 from offset 15
mirror "Mirror5"
sketch "Sketch1" plane through (0, -20, 0) normal (0, -1, 0) x axis (1, 0, 0)
  line L1 (43, 28.5) -> (-43, 28.5)
  line L2 (43, -28.5) -> (43, 28.5)
  line L3 (-43, -28.5) -> (43, -28.5)
  line L4 (-43, 28.5) -> (-43, -28.5)
  line L5 (0, 0) -> (0, 28.5)
  line L6 (43, 0) -> (0, 0)
  line L7 (-44.5, -30) -> (44.5, -30)
  line L8 (-44.5, 30) -> (-44.5, -30)
  line L9 (44.5, 30) -> (-44.5, 30)
  line L10 (44.5, -30) -> (44.5, 30)
  line L11 (7.5, -10) -> (-7.5, -10)
  line L12 (7.5, -30) -> (7.5, -10)
  line L13 (-7.5, -30) -> (7.5, -30)
  line L14 (-7.5, -10) -> (-7.5, -30)
  line L15 (5.5, 22.5) -> (-5.5, 22.5)
  line L16 (5.5, 13.5) -> (5.5, 22.5)
  line L17 (-5.5, 13.5) -> (5.5, 13.5)
  line L18 (-5.5, 22.5) -> (-5.5, 13.5)
  line L19 (0, 28.5) -> (0, 22.5)
  line L20 (-13, -21.4384) -> (-7.5, -25.4343)
  line L21 (-13, -12.4384) -> (-13, -21.4384)
  line L22 (13, -21.4384) -> (7.5, -25.4343)
  line L23 (13, -12.4384) -> (13, -21.4384)
  circle C1 centre (0, 0.0115) radius 11.2
  circle C2 centre (0, 0.0115) radius 18
  point P6 (0, 28.5)
  point P1 (0, 0)
  point P7 (0, 0)
  point P8 (43, 0)
  point P23 (0, 22.5)
  point P24 (-7.5, -25.4343)
  point P26 (-13, -12.4384)
  point P27 (7.5, -25.4343)
  point P25 (-13, -21.4384)
  point P28 (13, -21.4384)
  point P29 (13, -12.4384)
  point P2 (-43, 28.5)
  point P3 (43, 28.5)
  point P4 (43, -28.5)
  point P15 (-7.5, -10)
  point P16 (7.5, -10)
  point P18 (-7.5, -30)
  point P19 (-5.5, 22.5)
  point P20 (5.5, 22.5)
  point P22 (-5.5, 13.5)
  horizontal L1
  vertical L2
  horizontal L3
  vertical L4
  midpoint L1 P6
  coincident P1 P7
  midpoint L2 P8
  vertical L5
  horizontal L6
  concentric C1 C2
  horizontal L11
  vertical L12
  horizontal L13
  vertical L14
  midpoint L7 L13
  horizontal L15
  vertical L16
  horizontal L17
  vertical L18
  midpoint L15 P23
  vertical L19
  vertical L21
  coincident L14 P24
  coincident C2 P26
  symmetric L5 P24 P27
  symmetric L5 P25 P28
  symmetric L5 P26 P29
  dimension "d267" distance P2 P3 = 86 (= "boxWidth")
  dimension "d268" distance P3 P4 = 57 (= "boxHeight")
  dimension "d270" diameter C2 = 36
  dimension "d279" distance P15 P16 = 15
  dimension "d280" distance P15 P18 = 20
  dimension "d333" distance P19 P20 = 11
  dimension "d334" distance P19 P22 = 9
  dimension "d335" distance L1 L15 = 6
  dimension "d420" angle L14 L20 = 54
  dimension "d421" distance L14 L21 = 5.5
  dimension "d422" distance P25 P26 = 9
extrude "Extrude1" new body sketch "Sketch1" profile of L1 L2 L3 L4 L9 L8 L10 L7 C2 L12 L13 L14 L15 L16 L18 L20 L21 blind 1.5 (= "thickness") from offset 3
extrude "Extrude2" add sketch "Sketch1" profile of L1 L2 L3 L4 L9 L8 L10 L7 L12 L13 L14 to an object
fillet "Fillet1" radius 4 2.5
extrude "Extrude3" cut sketch "Sketch1" profile of L3 L7 C2 L11 L12 L13 L14 L15 L16 L17 L18 L20 L21 L22 L23 to an object
sketch "Sketch1" plane through (0, 0, 0) normal (1, 0, 0) x axis (0, 1, 0)
  line L1 (-19, 27.5) -> (-20, 28.5)
  line L2 (-18, 28.5) -> (-19, 27.5)
  line L3 (-16.9393, 27.4393) -> (-18, 28.5)
  line L4 (-19, 25.3787) -> (-16.9393, 27.4393)
  line L5 (-22.1213, 28.5) -> (-19, 25.3787)
  line L6 (-20, 28.5) -> (-22.1213, 28.5)
  line L7 (-20, 28.5) -> (-18, 28.5)
  line L8 (-13, 0) -> (0, 0)
  line L9 (-20, -28.5) -> (-22.1213, -28.5)
  line L10 (-19, -27.5) -> (-20, -28.5)
  line L11 (-18, -28.5) -> (-19, -27.5)
  line L12 (-16.9393, -27.4393) -> (-18, -28.5)
  line L13 (-19, -25.3787) -> (-16.9393, -27.4393)
  line L14 (-22.1213, -28.5) -> (-19, -25.3787)
  point P1 (0, 0)
  point P8 (0, 0)
  point P2 (-20, 28.5)
  point P11 (-20, -28.5)
  point P3 (-19, 27.5)
  point P12 (-19, -27.5)
  point P4 (-18, 28.5)
  point P13 (-18, -28.5)
  point P5 (-16.9393, 27.4393)
  point P14 (-16.9393, -27.4393)
  point P6 (-19, 25.3787)
  point P15 (-19, -25.3787)
  point P7 (-22.1213, 28.5)
  point P10 (-22.1213, -28.5)
  perpendicular L1 L2
  perpendicular L2 L3
  perpendicular L3 L4
  horizontal L6
  parallel L6 L7
  perpendicular L4 L5
  coincident P1 P8
  horizontal L8
  symmetric P2 L8 P11
  symmetric P3 L8 P12
  symmetric P4 L8 P13
  symmetric P5 L8 P14
  symmetric P6 L8 P15
  symmetric P7 L8 P10
  dimension "d284" distance P2 P4 = 2
  dimension "d285" distance P4 P5 = 1.5 (= "thickness")
  dimension "d287" distance L1 L5 = 1.5 (= "thickness")
  dimension "d288" distance P1 L6 = 28.5 (= "boxHeight / 2")
  dimension "d289" distance P1 P2 = 20
extrude "Extrude6" add sketch "Sketch1" profile of L1 L2 L3 L4 L5 L6 distance 30
offset_faces "OffsetFaces1" distance 0.2 (= "gap")
offset_faces "OffsetFaces2"
extrude "Extrude7" add sketch "Sketch1" profile of L9 L10 L11 L12 L13 L14 blind 18 from offset 15
mirror "Mirror2"
offset_faces "OffsetFaces3" distance 0.2 (= "gap")
offset_faces "OffsetFaces4"
sketch "Sketch2" plane through (0, 0, 0) normal (0, 0, 1) x axis (1, 0, 0)
  line L1 (-42, -19) -> (-43, -20)
  line L2 (-43, -18) -> (-42, -19)
  line L3 (-39.8787, -19) -> (-41.9393, -16.9393)
  line L4 (-43, -22.1213) -> (-39.8787, -19)
  line L5 (-43, -18) -> (-43, -20)
  line L6 (-43, -18) -> (-41.9393, -16.9393)
  line L7 (-43, -20) -> (-43, -22.1213)
  point P2 (-43, -20)
  point P4 (-43, -18)
  point P1 (0, 0)
  perpendicular L1 L2
  parallel L2 L3
  perpendicular L3 L4
  vertical L5
  perpendicular L3 L6
  vertical L7
  dimension "d308" distance P2 P4 = 2
  dimension "d310" distance L2 L3 = 1.5 (= "thickness")
  dimension "d312" distance P1 P2 = 20
  dimension "d314" angle L4 L7 = 45
  dimension "d315" distance L1 L4 = 1.5 (= "thickness")
  dimension "d316" distance P1 L5 = 43 (= "boxWidth / 2")
extrude "Extrude8" add sketch "Sketch2" profile of L1 L2 L3 L4 L6 L7 distance 20
mirror "Mirror3"
offset_faces "OffsetFaces5" distance 0.2 (= "gap")
offset_faces "OffsetFaces6"
fillet "Fillet2" radius 0.5
chamfer "Chamfer1" distance 1
chamfer "Chamfer2" distance 2
fillet "Fillet3" radius 1
sketch "Sketch1" plane through (0, 7, 0) normal (0, 1, 0) x axis (-1, 0, 0)
  line L1 (44.5, 30) -> (-44.5, 30)
  line L2 (44.5, -30) -> (44.5, 30)
  line L3 (-44.5, -30) -> (44.5, -30)
  line L4 (-44.5, 30) -> (-44.5, -30)
  line L5 (0, 0) -> (0, 30)
  line L6 (44.5, 0) -> (0, 0)
  point P6 (0, 30)
  point P1 (0, 0)
  point P7 (0, 0)
  point P8 (44.5, 0)
  point P2 (-44.5, 30)
  point P3 (44.5, 30)
  point P5 (-44.5, -30)
  horizontal L1
  vertical L2
  horizontal L3
  vertical L4
  midpoint L1 P6
  coincident P1 P7
  midpoint L2 P8
  horizontal L6
  vertical L5
  dimension "d342" distance P2 P3 = 89 (= "boxWidth + ( thickness * 2 )")
  dimension "d343" distance P2 P5 = 60 (= "boxHeight + ( thickness * 2 )")
extrude "Extrude1" new body sketch "Sketch1" profile of L1 L2 L3 L4 blind 1.5 (= "thickness") from offset 2
fillet "Fillet1" radius 4
sketch "Sketch2" plane through (0, 9, 0) normal (0, -1, 0) x axis (1, 0, 0)
  line L1 (40.5, -30) -> (-40.5, -30)
  line L2 (44.5, 26) -> (44.5, -26)
  line L3 (-40.5, 30) -> (40.5, 30)
  line L4 (-44.5, -26) -> (-44.5, 26)
  line L5 (-43, -26) -> (-43, 26)
  line L6 (40.5, -28.5) -> (-40.5, -28.5)
  line L7 (43, 26) -> (43, -26)
  line L8 (-40.5, 28.5) -> (40.5, 28.5)
  line L9 (23.5, 26) -> (44.5, 26)
  line L10 (23.5, -26) -> (23.5, 26)
  line L11 (44.5, -26) -> (23.5, -26)
  line L12 (28.1, -6) -> (28.1, 26)
  line L13 (23.5, -6) -> (28.1, -6)
  line L14 (-36, -21.76) -> (16, -21.76)
  line L15 (-36, -27.24) -> (-36, -21.76)
  line L16 (16, -27.24) -> (-36, -27.24)
  line L17 (16, -21.76) -> (16, -27.24)
  line L18 (15.4, -24.1) -> (15.4, -22.36)
  line L19 (15, -21.96) -> (13.26, -21.96)
  line L20 (-35.4, -24.9) -> (-35.4, -26.64)
  line L21 (-35, -27.04) -> (-33.26, -27.04)
  line L22 (16.66, -16.02) -> (21.34, -16.02)
  line L23 (16.66, -20.7) -> (16.66, -16.02)
  line L24 (21.34, -20.7) -> (16.66, -20.7)
  line L25 (21.34, -16.02) -> (21.34, -20.7)
  line L26 (18.6, -20.9) -> (16.86, -20.9)
  line L27 (16.46, -20.5) -> (16.46, -18.76)
  line L28 (19.4, -15.82) -> (21.14, -15.82)
  line L29 (21.54, -16.22) -> (21.54, -17.96)
  line L30 (44.5, 12) -> (28.1, 12)
  line L31 (44.5, 8) -> (28.1, 8)
  line L32 (44.5, -6) -> (28.1, -6)
  line L33 (44.5, -9.4) -> (23.5, -9.4)
  line L34 (2.1841, 25.0033) -> (4.1841, 25.0033)
  line L35 (2.1841, 8.0033) -> (2.1841, 25.0033)
  line L36 (4.1841, 8.0033) -> (2.1841, 8.0033)
  line L37 (4.1841, 25.0033) -> (4.1841, 8.0033)
  line L38 (-38.6741, 8.4951) -> (-36.6741, 8.4951)
  line L39 (-38.6741, -8.5049) -> (-38.6741, 8.4951)
  line L40 (-36.6741, -8.5049) -> (-38.6741, -8.5049)
  line L41 (-36.6741, 8.4951) -> (-36.6741, -8.5049)
  line L42 (10.92, -21.76) -> (16.66, -16.02)
  line L43 (16, -26.04) -> (21.34, -20.7)
  arc A1 centre (-40.5, -26) radius 4 clockwise from (-40.5, -30) to (-44.5, -26)
  arc A2 centre (40.5, -26) radius 4 clockwise from (44.5, -26) to (40.5, -30)
  arc A3 centre (40.5, 26) radius 4 clockwise from (40.5, 30) to (44.5, 26)
  arc A4 centre (-40.5, 26) radius 4 clockwise from (-44.5, 26) to (-40.5, 30)
  arc A5 centre (-40.5, -26) radius 2.5 clockwise from (-40.5, -28.5) to (-43, -26)
  arc A6 centre (40.5, -26) radius 2.5 clockwise from (43, -26) to (40.5, -28.5)
  arc A7 centre (40.5, 26) radius 2.5 clockwise from (40.5, 28.5) to (43, 26)
  arc A8 centre (-40.5, 26) radius 2.5 clockwise from (-43, 26) to (-40.5, 28.5)
  point P8 (44.5, 26)
  point P26 (44.5, 26)
  point P6 (44.5, -26)
  point P29 (44.5, -26)
  point P30 (28.1, 26)
  point P32 (23.5, -6)
  point P57 (28.1, 12)
  point P58 (44.5, 12)
  point P59 (28.1, 8)
  point P60 (44.5, 8)
  point P61 (44.5, -6)
  point P62 (23.5, -9.4)
  point P63 (44.5, -9.4)
  point P72 (10.92, -21.76)
  point P73 (16, -26.04)
  point P27 (23.5, 26)
  point P31 (28.1, -6)
  point P66 (2.1841, 8.0033)
  point P67 (4.1841, 8.0033)
  point P65 (2.1841, 25.0033)
  point P68 (-36.6741, 8.4951)
  point P69 (-38.6741, 8.4951)
  point P71 (-36.6741, -8.5049)
  coincident P8 P26
  perpendicular L2 L9
  coincident P6 P29
  perpendicular L10 L11
  perpendicular L9 L10
  coincident L9 P30
  perpendicular L9 L12
  coincident L10 P32
  horizontal L14
  vertical L15
  horizontal L16
  vertical L17
  horizontal L22
  vertical L23
  horizontal L24
  vertical L25
  coincident L12 P57
  coincident L2 P58
  perpendicular L2 L30
  coincident L12 P59
  coincident L2 P60
  perpendicular L2 L31
  horizontal L13
  coincident L2 P61
  perpendicular L2 L32
  coincident L10 P62
  coincident L2 P63
  perpendicular L7 L33
  horizontal L34
  vertical L35
  horizontal L36
  vertical L37
  horizontal L38
  vertical L39
  horizontal L40
  vertical L41
  coincident L14 P72
  coincident L17 P73
  dimension "d351" distance P26 P27 = 21
  dimension "d353" distance P30 P31 = 32
  dimension "d354" distance L10 L12 = 4.6
  dimension "d370" distance L16 L21 = 0.2 (= "gap")
  dimension "d371" distance L15 L20 = 0.6 (= "gap * 3")
  dimension "d372" distance L14 L19 = 0.2 (= "gap")
  dimension "d373" distance L17 L18 = 0.6 (= "gap * 3")
  dimension "d380" distance L13 L33 = 3.4
  dimension "d381" distance L9 L30 = 14
  dimension "d382" distance L30 L31 = 4
  dimension "d383" distance P66 P67 = 2
  dimension "d384" distance P65 P66 = 17
  dimension "d385" distance P68 P69 = 2
  dimension "d386" distance P68 P71 = 17
  dimension "d389" distance L24 L26 = 0.2 (= "gap")
  dimension "d390" distance L23 L27 = 0.2 (= "gap")
  dimension "d391" distance L22 L28 = 0.2 (= "gap")
  dimension "d392" distance L25 L29 = 0.2 (= "gap")
  dimension "d418" angle L14 L42 = 45
  dimension "d419" angle L24 L43 = 45
extrude "Extrude2" add sketch "Sketch2" profile of A1 L1 A2 L2 A3 L3 A4 L4 A8 L8 A7 A6 L7 L6 A5 L5 along normal blind 2
extrude "Extrude3" sketch "Sketch2" profile of L2 L7 L9 L10 L11 L12 L30 L31 L32 L33 to an object
fillet "Fillet2" radius 1
sketch "Sketch3" plane through (0, 0, 30) normal (0, 0, 1) x axis (-1, 0, 0)
  line L1 (7, -1) -> (-1, -1)
  line L2 (20, -1) -> (13, -1)
  line L3 (36, -1) -> (26, -1)
  line L4 (36, -5) -> (-1, -5)
  line L5 (36, -7) -> (36, -5)
  line L6 (-1, -7) -> (36, -7)
  line L7 (-1, -5) -> (-1, -7)
  line L8 (7, -4) -> (7, -5)
  line L9 (13, -4) -> (7, -4)
  line L10 (13, -5) -> (13, -4)
  line L11 (20, -4) -> (20, -5)
  line L12 (26, -4) -> (20, -4)
  line L13 (26, -5) -> (26, -4)
  circle C1 centre (-11.5, -4.59) radius 2.1
  circle C2 centre (-11.5, -4.59) radius 3.5
  point P9 (36, -1)
  point P4 (-1, -1)
  point P14 (7, -5)
  point P17 (13, -5)
  point P6 (13, -1)
  point P5 (7, -1)
  point P18 (20, -5)
  point P21 (26, -5)
  point P7 (20, -1)
  point P8 (26, -1)
  point P11 (36, -5)
  point P12 (36, -7)
  point P1 (0, 0)
  point P15 (7, -4)
  point P20 (26, -4)
  concentric C1 C2
  horizontal L4
  vertical L5
  horizontal L6
  vertical L7
  coincident P9 L5
  coincident P4 L7
  coincident L4 P14
  perpendicular L4 L8
  perpendicular L8 L9
  coincident L4 P17
  perpendicular L4 L10
  coincident P6 L10
  coincident P5 L8
  coincident L4 P18
  perpendicular L4 L11
  perpendicular L11 L12
  coincident L4 P21
  perpendicular L4 L13
  coincident P7 L11
  coincident P8 L13
  dimension "d359" diameter C2 = 7
  dimension "d360" distance P11 P12 = 2
  dimension "d361" distance P1 L6 = 7
  dimension "d362" distance P14 P15 = 1
  dimension "d363" distance P20 P21 = 1
extrude "Extrude4" add sketch "Sketch3" profile of L4 L5 L6 L7 L8 L9 L10 L11 L12 L13 no distance stored
fillet "Fillet3" radius 1
extrude "Extrude5" cut sketch "Sketch3" profile of C1 C2 no distance stored
fillet "Fillet4" radius 1
extrude "Extrude6" cut sketch "Sketch2" profile of L14 L15 L16 L17 L22 L23 L24 L25 L34 L35 L36 L37 L38 L39 L40 L41 no distance stored
fillet "Fillet5" radius 1
chamfer "Chamfer1" distance 1
sketch "Sketch4" plane through (0, 0, 0) normal (1, 0, 0) x axis (0, 1, 0)
  line L1 (4.5, -27) -> (8.5, -27)
  line L2 (4.5, -28.5) -> (4.5, -27)
  line L3 (8.5, -28.5) -> (4.5, -28.5)
  line L4 (8.5, -27) -> (8.5, -28.5)
  point P2 (8.5, -27)
  point P5 (8.5, -28.5)
  point P3 (4.5, -27)
  point P1 (0, 0)
  horizontal L1
  vertical L2
  horizontal L3
  vertical L4
  dimension "d393" distance P2 P5 = 1.5 (= "thickness")
  dimension "d394" distance P2 P3 = 4
  dimension "d395" distance P1 L3 = 28.5 (= "boxHeight / 2")
  dimension "d396" distance P1 L4 = 8.5
sketch "Sketch5" plane through (0, 0, 0) normal (0, 0, 1) x axis (1, 0, 0)
  line L1 (-41.5, 8.5) -> (-43, 8.5)
  line L2 (-41.5, 4.5) -> (-41.5, 8.5)
  line L3 (-43, 4.5) -> (-41.5, 4.5)
  line L4 (-43, 8.5) -> (-43, 4.5)
  point P3 (-41.5, 8.5)
  point P4 (-41.5, 4.5)
  point P5 (-43, 4.5)
  point P1 (0, 0)
  horizontal L1
  vertical L2
  horizontal L3
  vertical L4
  dimension "d403" distance P3 P4 = 4
  dimension "d404" distance P4 P5 = 1.5 (= "thickness")
  dimension "d405" distance P1 L4 = 43 (= "boxWidth / 2")
  dimension "d406" distance P1 L1 = 8.5
extrude "Extrude8" add sketch "Sketch5" distance 20
chamfer "Chamfer3" distance 1.5 (= "thickness")
fillet "Fillet7" radius 1
offset_faces "OffsetFaces3" distance 0.2 (= "gap")
offset_faces "OffsetFaces4"
chamfer "Chamfer4" distance 1
sketch "Sketch5" plane through (0, 0, -28.5) normal (0, 0, 1) x axis (-1, 0, 0)
  line L1 (-7.5, 20) -> (-7.5, 22.5)
  line L2 (7.5, 22.5) -> (7.5, 20)
  line L3 (-7.5, 17) -> (7.5, 17)
  line L4 (-7.5, 20) -> (-7.5, 17)
  line L5 (7.5, 20) -> (-7.5, 20)
  line L6 (7.5, 17) -> (7.5, 20)
  point P3 (-7.5, 20)
  point P8 (-7.5, 20)
  point P4 (7.5, 20)
  point P9 (7.5, 20)
  point P6 (7.5, 17)
  horizontal L3
  vertical L4
  horizontal L5
  vertical L6
  coincident P3 P8
  coincident P4 P9
  dimension "d414" distance P6 P9 = 3
extrude "Extrude9" cut sketch "Sketch5" profile of L3 L4 L5 L6 no distance stored
sketch "cam cable cut" plane through (0, 0, -30) normal (0, 0, -1) x axis (1, 0, 0)
  line L1 (-8, -5) -> (8, -5)
  line L2 (-8, -7) -> (-8, -5)
  line L3 (8, -7) -> (-8, -7)
  line L4 (8, -5) -> (8, -7)
  line L5 (0, 0) -> (0, -5)
  point P6 (0, -5)
  point P1 (0, 0)
  point P7 (0, 0)
  point P4 (-8, -7)
  point P5 (8, -7)
  point P3 (-8, -5)
  horizontal L1
  vertical L2
  horizontal L3
  vertical L4
  midpoint L1 P6
  coincident P1 P7
  vertical L5
  dimension "d423" distance P4 P5 = 16
  dimension "d424" distance P3 P4 = 2
  dimension "d425" distance P6 P7 = 5
extrude "Extrude12" cut sketch "cam cable cut" profile of L1 L2 L3 L4 no distance stored
chamfer "Chamfer1" distance 2
base_feature "Base Feature1"
rectangular_pattern "" uSpaceDistance 6 vSpaceDistance 0
joint "Assemble19" alignAngle 0 alignOffsetX 0 alignOffsetY 0 alignOffsetZ 0
joint "Assemble20" alignAngle 0 alignOffsetX 0 alignOffsetY 0 alignOffsetZ 0
joint "Assemble21" alignAngle 0 alignOffsetX 0 alignOffsetY 0 alignOffsetZ 0
joint "Assemble22" alignAngle 0 alignOffsetX 0 alignOffsetY 0 alignOffsetZ 0
base_feature "Base Feature1"
rectangular_pattern "ꨁ236" uSpaceDistance -13 vSpaceDistance 0
joint "Assemble23" alignAngle 0 alignOffsetX 0 alignOffsetY 0 alignOffsetZ 0
joint "Assemble24" alignAngle 0 alignOffsetX 0 alignOffsetY 0 alignOffsetZ 0
joint "Assemble25" alignAngle 0 alignOffsetX 0 alignOffsetY 0 alignOffsetZ 0
joint "Assemble26" alignAngle 0 alignOffsetX 0 alignOffsetY 0 alignOffsetZ 0
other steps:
create_component "CreateComponent1"
create_component "CreateComponent2"
create_component "CreateComponent1"
joint_origin "JointOrigin1" sketch "base" OffsetX 0 OffsetY 0 OffsetZ 0 AngleZ 0
create_component "CreateComponent2"
create_component "CreateComponent3"
create_component "CreateComponent3"
joint_origin "JointOrigin4" OffsetX 0 OffsetY 0 OffsetZ 0 AngleZ 0
create_component "CreateComponent4"
create_component "CreateComponent5"
create_component "CreateComponent1"
create_component "CreateComponent2"
create_component "CreateComponent1"
joint_origin "JointOrigin1" OffsetX 0 OffsetY 0 OffsetZ 0 AngleZ 0
joint_origin "JointOrigin1" OffsetX 0 OffsetY 0 OffsetZ 0 AngleZ 0
joint_origin "JointOrigin2" OffsetX 0 OffsetY 0 OffsetZ 0 AngleZ 0
joint_origin "JointOrigin2" OffsetX 0 OffsetY 0 OffsetZ 0 AngleZ 0
joint_origin "JointOrigin3" OffsetX 0 OffsetY 0 OffsetZ 0 AngleZ 0
joint_origin "JointOrigin3" OffsetX 0 OffsetY 0 OffsetZ 0 AngleZ 0
joint_origin "JointOrigin4" OffsetX 0 OffsetY 0 OffsetZ 0 AngleZ 0
joint_origin "JointOrigin4" OffsetX 0 OffsetY 0 OffsetZ 0 AngleZ 0
joint_origin "JointOrigin5" OffsetX 0 OffsetY 0 OffsetZ 0 AngleZ 0
joint_origin "JointOrigin6" OffsetX 0 OffsetY 0 OffsetZ 0 AngleZ 0
joint_origin "JointOrigin7" OffsetX 0 OffsetY 0 OffsetZ 0 AngleZ 0
joint_origin "JointOrigin8" OffsetX 0 OffsetY 0 OffsetZ 0 AngleZ 0
create_component "CreateComponent3"
create_component "CreateComponent1"
joint_origin "JointOrigin1" OffsetX 0 OffsetY 0 OffsetZ 0 AngleZ 0
joint_origin "JointOrigin2" OffsetX 0 OffsetY 0 OffsetZ 0 AngleZ 0
joint_origin "JointOrigin3" OffsetX 0 OffsetY 0 OffsetZ 0 AngleZ 0
joint_origin "JointOrigin4" OffsetX 0 OffsetY 0 OffsetZ 0 AngleZ 0
create_component "CreateComponent4"
create_component "CreateComponent1"
joint_origin "JointOrigin1" OffsetX 0 OffsetY 0 OffsetZ 0 AngleZ 0
joint_origin "JointOrigin5" OffsetX 0 OffsetY 0 OffsetZ 0 AngleZ 0
joint_origin "JointOrigin2" OffsetX 0 OffsetY 0 OffsetZ 0 AngleZ 0
joint_origin "JointOrigin6" OffsetX 0 OffsetY 0 OffsetZ 0 AngleZ 0
joint_origin "JointOrigin3" OffsetX 0 OffsetY 0 OffsetZ 0 AngleZ 0
joint_origin "JointOrigin7" OffsetX 0 OffsetY 0 OffsetZ 0 AngleZ 0
joint_origin "JointOrigin4" OffsetX 0 OffsetY 0 OffsetZ 0 AngleZ 0
joint_origin "JointOrigin8" OffsetX 0 OffsetY 0 OffsetZ 0 AngleZ 0
create_component "CreateComponent5"
create_component "CreateComponent1"
joint_origin "JointOrigin1" OffsetX 0 OffsetY 0 OffsetZ 0 AngleZ 0
joint_origin "JointOrigin9" OffsetX 0 OffsetY 0 OffsetZ 0 AngleZ 0
joint_origin "JointOrigin2" OffsetX 0 OffsetY 0 OffsetZ 0 AngleZ 0
joint_origin "JointOrigin10" OffsetX 0 OffsetY 0 OffsetZ 0 AngleZ 0
joint_origin "JointOrigin3" OffsetX 0 OffsetY 0 OffsetZ 0 AngleZ 0
joint_origin "JointOrigin11" OffsetX 0 OffsetY 0 OffsetZ 0 AngleZ 0
joint_origin "JointOrigin4" OffsetX 0 OffsetY 0 OffsetZ 0 AngleZ 0
joint_origin "JointOrigin12" OffsetX 0 OffsetY 0 OffsetZ 0 AngleZ 0
create_component "CreateComponent6"
create_component "CreateComponent1"
joint_origin "JointOrigin1" OffsetX 0 OffsetY 0 OffsetZ 0 AngleZ 0
joint_origin "JointOrigin5" OffsetX 0 OffsetY 0 OffsetZ 0 AngleZ 0
joint_origin "JointOrigin2" OffsetX 0 OffsetY 0 OffsetZ 0 AngleZ 0
joint_origin "JointOrigin6" OffsetX 0 OffsetY 0 OffsetZ 0 AngleZ 0
joint_origin "JointOrigin3" OffsetX 0 OffsetY 0 OffsetZ 0 AngleZ 0
joint_origin "JointOrigin7" OffsetX 0 OffsetY 0 OffsetZ 0 AngleZ 0
joint_origin "JointOrigin4" OffsetX 0 OffsetY 0 OffsetZ 0 AngleZ 0
joint_origin "JointOrigin8" OffsetX 0 OffsetY 0 OffsetZ 0 AngleZ 0
create_component "CreateComponent1"
create_component "CreateComponent2"
create_component "CreateComponent3"
create_component "CreateComponent4"
create_component "CreateComponent5"
create_component "CreateComponent6"
create_component "CreateComponent7"
create_component "CreateComponent8"
create_component "CreateComponent9"
create_component "CreateComponent10"
create_component "CreateComponent11"
create_component "CreateComponent12"
create_component "CreateComponent13"
create_component "CreateComponent14"
create_component "CreateComponent15"
create_component "CreateComponent16"
create_component "CreateComponent17"
create_component "CreateComponent18"
create_component "CreateComponent1"
create_component "CreateComponent1"
create_component "CreateComponent2"
named bodies: "pcb-mount", "frame", "front-case", "front-cover", "back-cover"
